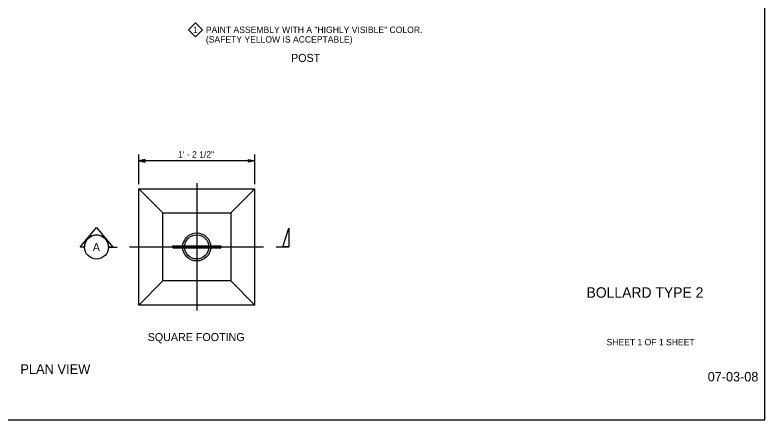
# Model space of a CAD drawing. Extents: x 99862 to 103151, y 100000 to 102076.
# Drawn here: x 101278 to 103151, y 100000 to 101010 of the extents above; entities that cross this region are included whole.
import ezdxf

# ---------------------------------------------------------------- set-up
doc = ezdxf.new("R2010")
doc.units = 0
for name, color, linetype in [('Level 1', 7, 'Continuous'), ('Level 15', 7, 'Continuous'), ('Level 20', 7, 'Continuous'), ('Level 60', 7, 'Continuous'), ('Level 62', 7, 'Continuous'), ('Level 9', 7, 'Continuous')]:
    doc.layers.add(name, color=color, linetype=linetype)

msp = doc.modelspace()

# ---------------------------------------------------------------- linework, layer by layer
at = {"layer": 'Level 1'}
for p, q in [((101587.4, 100286.5), (101587.4, 100576.5)), ((101587.4, 100576.5), (101877.4, 100576.5)), ((101647.1, 100516.5), (101587.4, 100576.5)), ((101817.1, 100516.5), (101877.4, 100576.5)), ((101877.4, 100286.5), (101877.4, 100576.5)), ((101647.1, 100516.5), (101817.1, 100516.5)), ((101672.1, 100429), (101672.1, 100434)), ((101672.1, 100434), (101792.1, 100434)), ((101792.1, 100434), (101792.1, 100429)), ((101672.1, 100429), (101792.1, 100429)), ((101647.1, 100346.5), (101587.4, 100286.5)), ((101817.1, 100346.5), (101877.4, 100286.5)), ((101877.4, 100286.5), (101587.4, 100286.5))]:
    msp.add_line(p, q, dxfattribs=at)
msp.add_lwpolyline([(101817.1, 100516.5), (101817.1, 100346.5), (101647.1, 100346.5), (101647.1, 100516.5)], dxfattribs=at)
for radius in [35, 30.1]:
    msp.add_circle((101732.1, 100431.5), radius, dxfattribs=at)
at = {"layer": 'Level 15'}
for p, q in [((101587.4, 100588.5), (101587.4, 100662.5)), ((101877.4, 100588.5), (101877.4, 100662.5)), ((101877.4, 100646.5), (101587.4, 100646.5)), ((101732.1, 100590.9), (101732.1, 100273)), ((101564.6, 100431.5), (101898.5, 100431.5))]:
    msp.add_line(p, q, dxfattribs=at)
for points in [[(101587.4, 100646.5), (101603.2, 100643.4), (101602.4, 100646.5), (101603.2, 100649.5)], [(101877.4, 100646.5), (101861.7, 100643.4), (101862.4, 100646.5), (101861.7, 100649.5)]]:
    msp.add_lwpolyline(points, close=True, dxfattribs=at)
at = {"layer": 'Level 20'}
msp.add_lwpolyline([(101729.4, 100991.1), (101746.9, 100973.6), (101729.4, 100956), (101711.8, 100973.6)], close=True, dxfattribs=at)
at = {"layer": 'Level 60'}
msp.add_lwpolyline([(99862, 99999.5), (103151, 99999.5), (103151, 102075.5), (99862, 102075.5)], close=True, dxfattribs=at)
at = {"layer": 'Level 9'}
for p, q in [((101441.3, 100431.3), (101481.9, 100479.8)), ((101481.9, 100479.8), (101522.5, 100431.3)), ((101451.9, 100431.3), (101441.3, 100431.3)), ((101522.5, 100431.3), (101511.9, 100431.3)), ((101511.9, 100431.3), (101533.7, 100431.3)), ((101930.8, 100431.5), (101962.4, 100431.5))]:
    msp.add_line(p, q, dxfattribs=at)
msp.add_lwpolyline([(101946.9, 100431.5), (101962.4, 100478.3), (101962.4, 100431.5)], close=True, dxfattribs=at)
msp.add_circle((101481.9, 100431.3), 30, dxfattribs=at)
msp.add_arc((101481.9, 100431.3), 30, 359.9978, 180.0022, dxfattribs=at)

# ---------------------------------------------------------------- texts
at = {"layer": 'Level 1'}
msp.add_text('07-03-08', height=23.62, dxfattribs=at).set_placement((103008, 100095.8))
at = {"layer": 'Level 20'}
for s, height, p in [('1', 16, (101722.5, 100965.6)), ('PAINT ASSEMBLY WITH A "HIGHLY VISIBLE" COLOR.', 16, (101754.9, 100965.6)), ('(SAFETY YELLOW IS ACCEPTABLE)', 16, (101754.9, 100941.6)), ('POST', 20, (101967.7, 100893.4)), ('1\' - 2 1/2"', 16, (101685.4, 100654.5)), ('SQUARE FOOTING', 20, (101609.6, 100196.5)), ('PLAN VIEW', 24, (101291.6, 100114.5))]:
    msp.add_text(s, height=height, dxfattribs=at).set_placement(p)
msp.add_text('A', height=20, rotation=0, dxfattribs=at).set_placement((101472.6, 100421.3))
at = {"layer": 'Level 62'}
for s, height, p in [(' BOLLARD TYPE 2', 26, (102695.7, 100304.8)), ('SHEET 1 OF 1 SHEET', 16, (102755.4, 100185.9))]:
    msp.add_text(s, height=height, dxfattribs=at).set_placement(p)

doc.saveas('drawing.dxf')
